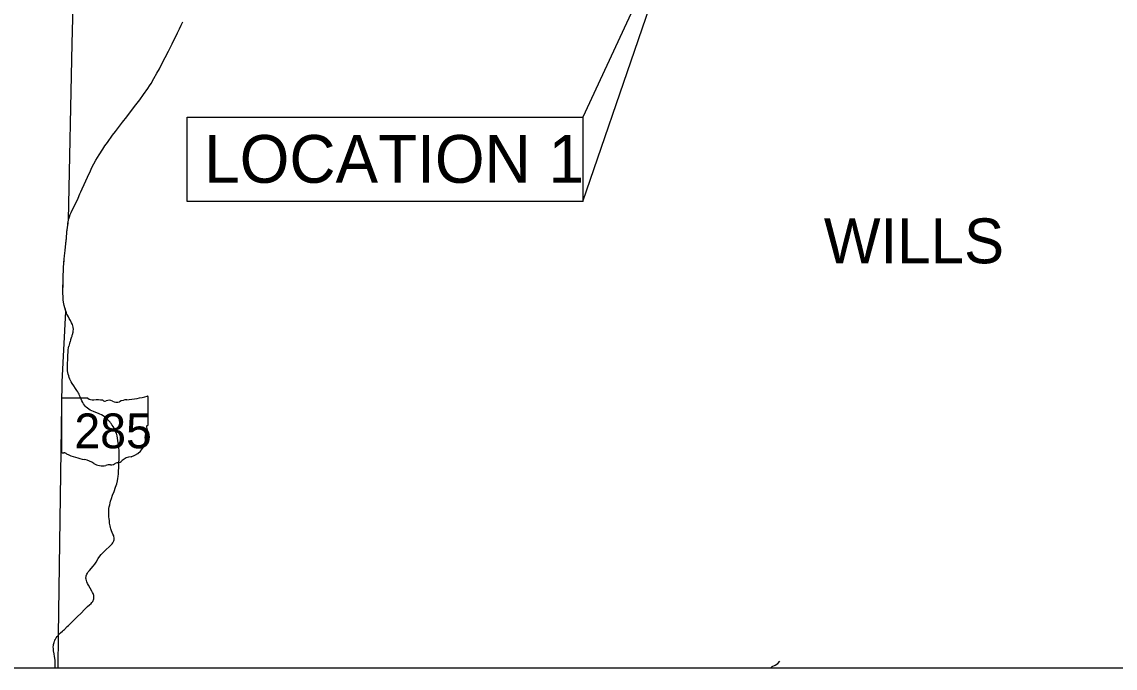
# Model space of a CAD drawing. Extents: x -29.6 to 34, y 0 to 22.
# Drawn here: x -18.092 to -14.201, y 1.053 to 3.352 of the extents above; entities that cross this region are included whole.
import ezdxf

# ---------------------------------------------------------------- set-up
doc = ezdxf.new("R2010")
doc.units = 0
for name, color, linetype in [('BR_P_Gen_Text', 7, 'Continuous'), ('GM_X_Minor_River', 7, 'Continuous'), ('GM_X_State_Location', 7, 'Continuous'), ('GM_X_State_Route', 7, 'Continuous'), ('GM_X_State_Shield', 7, 'Continuous'), ('GM_X_Township', 7, 'Continuous'), ('GM_X_Township_Text', 7, 'Continuous'), ('SH_Text', 7, 'Continuous')]:
    doc.layers.add(name, color=color, linetype=linetype)

msp = doc.modelspace()

# ---------------------------------------------------------------- linework, layer by layer
at = {"layer": 'BR_P_Gen_Text'}
for points in [[(-16.0951, 3.013), (-16.0951, 2.7127), (-15.6989, 3.8667)], [(-17.5038, 3.013), (-16.0951, 3.013), (-16.0951, 2.7127), (-17.5038, 2.7127)]]:
    msp.add_lwpolyline(points, close=True, dxfattribs=at)
at = {"layer": 'GM_X_Minor_River'}
msp.add_lwpolyline([(-15.4272, 1.0528), (-15.4222, 1.0581), (-15.4116, 1.0629), (-15.4017, 1.069), (-15.3947, 1.078)], dxfattribs=at)
at = {"layer": 'GM_X_State_Route'}
for points in [[(-17.8771, 2.7585), (-17.8703, 2.774), (-17.8584, 2.7999), (-17.8478, 2.8226), (-17.8422, 2.8341), (-17.8351, 2.8474), (-17.828, 2.8601), (-17.8167, 2.8791), (-17.8039, 2.8993), (-17.7959, 2.9114), (-17.7875, 2.9232), (-17.7689, 2.9486), (-17.7585, 2.9626), (-17.733, 2.9952), (-17.7185, 3.0142), (-17.6906, 3.0508), (-17.6723, 3.0749), (-17.6586, 3.0937), (-17.6438, 3.1147), (-17.6373, 3.1244), (-17.6317, 3.1333), (-17.6216, 3.1504), (-17.6111, 3.1692), (-17.6023, 3.1857), (-17.5925, 3.2049), (-17.5818, 3.2256), (-17.5702, 3.2484), (-17.5573, 3.2739), (-17.5376, 3.3129), (-17.5307, 3.327), (-17.5246, 3.3403), (-17.5194, 3.3527)], [(-17.9254, 2.6468), (-17.9243, 2.6518), (-17.9222, 2.659), (-17.9196, 2.6667), (-17.9165, 2.6741), (-17.9117, 2.6841), (-17.9058, 2.6954), (-17.9017, 2.7031), (-17.896, 2.7146), (-17.8915, 2.7248), (-17.8851, 2.7398), (-17.8819, 2.7473), (-17.8771, 2.7585)], [(-17.9351, 2.3229), (-17.937, 2.329), (-17.938, 2.3323), (-17.9385, 2.334), (-17.9409, 2.3429), (-17.9423, 2.3485), (-17.9433, 2.3548), (-17.9442, 2.3628), (-17.945, 2.375), (-17.9454, 2.3855), (-17.9455, 2.3895), (-17.9455, 2.3907), (-17.9456, 2.3953), (-17.9456, 2.3999), (-17.9453, 2.4127), (-17.945, 2.4214), (-17.9445, 2.4418), (-17.9432, 2.4744), (-17.9419, 2.497), (-17.9417, 2.4993), (-17.9415, 2.5022), (-17.941, 2.5063), (-17.9408, 2.508), (-17.9395, 2.5195), (-17.9376, 2.5387), (-17.935, 2.563), (-17.9331, 2.5832), (-17.9311, 2.6041), (-17.9292, 2.6203), (-17.9281, 2.629), (-17.9274, 2.6342), (-17.9265, 2.641), (-17.9256, 2.646), (-17.9254, 2.6468)], [(-17.9612, 1.1708), (-17.9586, 1.1735), (-17.9561, 1.1759), (-17.9537, 1.1784), (-17.9473, 1.1843), (-17.9439, 1.1874), (-17.9405, 1.1905), (-17.9299, 1.2005), (-17.9253, 1.2049), (-17.9204, 1.2099), (-17.916, 1.2145), (-17.9118, 1.2185), (-17.9011, 1.2292), (-17.8944, 1.2355), (-17.8812, 1.2481), (-17.8683, 1.2611), (-17.8578, 1.2717), (-17.8505, 1.2784), (-17.8454, 1.2833), (-17.8426, 1.2863), (-17.8397, 1.29), (-17.8379, 1.2932), (-17.8368, 1.296), (-17.8358, 1.2995), (-17.8355, 1.3018), (-17.8354, 1.306), (-17.836, 1.3108), (-17.8371, 1.3148), (-17.8383, 1.3182), (-17.8398, 1.3214), (-17.8428, 1.3271), (-17.8491, 1.3376), (-17.8548, 1.3476), (-17.8581, 1.3541), (-17.8604, 1.3596), (-17.8621, 1.3645), (-17.8632, 1.3688), (-17.8638, 1.3731), (-17.8634, 1.3792), (-17.8626, 1.3816), (-17.8603, 1.3868), (-17.8583, 1.3902), (-17.8552, 1.395), (-17.8513, 1.4), (-17.8377, 1.4157), (-17.8322, 1.4226), (-17.8276, 1.4293), (-17.8197, 1.4423), (-17.8145, 1.4506), (-17.8094, 1.4575), (-17.8051, 1.4621), (-17.8015, 1.4658), (-17.7926, 1.4741), (-17.7797, 1.4858), (-17.7734, 1.4919), (-17.7707, 1.495), (-17.7678, 1.4988), (-17.7656, 1.503), (-17.7647, 1.5052), (-17.7636, 1.5093), (-17.7634, 1.5111), (-17.7631, 1.5165), (-17.7642, 1.5217), (-17.7647, 1.5235), (-17.7675, 1.5299), (-17.7705, 1.5357), (-17.7731, 1.5414), (-17.7753, 1.548), (-17.7767, 1.5536), (-17.7778, 1.5592), (-17.7793, 1.5684), (-17.7804, 1.5776), (-17.7812, 1.584), (-17.7819, 1.5908), (-17.7825, 1.5978), (-17.7828, 1.6058), (-17.7825, 1.6122), (-17.7818, 1.6202), (-17.7806, 1.6271), (-17.7792, 1.6339), (-17.7776, 1.6406), (-17.7757, 1.6473), (-17.7726, 1.6567), (-17.7686, 1.6676), (-17.7636, 1.6813), (-17.7582, 1.6961), (-17.7537, 1.7089), (-17.7509, 1.7194), (-17.7497, 1.7272), (-17.7486, 1.7344), (-17.7478, 1.744), (-17.7461, 1.7759), (-17.7452, 1.8033), (-17.7454, 1.8246), (-17.7464, 1.8389), (-17.75, 1.8624), (-17.7531, 1.8792), (-17.7555, 1.8883), (-17.7583, 1.8947), (-17.7608, 1.9007), (-17.7636, 1.9065), (-17.7668, 1.9121), (-17.77, 1.9171), (-17.7713, 1.919), (-17.7743, 1.9232), (-17.7761, 1.9254), (-17.7778, 1.9276), (-17.7792, 1.9293), (-17.7819, 1.9324), (-17.7871, 1.938), (-17.7921, 1.9429), (-17.7971, 1.9471), (-17.8018, 1.9506), (-17.8079, 1.9542), (-17.8137, 1.9569), (-17.8192, 1.959), (-17.829, 1.9624), (-17.8371, 1.9654), (-17.8429, 1.968), (-17.8484, 1.9709), (-17.8533, 1.9739), (-17.8583, 1.9777), (-17.8623, 1.981), (-17.8659, 1.9847), (-17.8691, 1.9886), (-17.872, 1.9929), (-17.8749, 1.9979), (-17.8779, 2.0041), (-17.8841, 2.0178), (-17.8853, 2.0207), (-17.8864, 2.0231), (-17.8882, 2.0273), (-17.8903, 2.0314), (-17.8926, 2.0355), (-17.8959, 2.0409), (-17.9007, 2.0482), (-17.9073, 2.0576), (-17.9129, 2.0655), (-17.9165, 2.0714), (-17.9192, 2.0764), (-17.9212, 2.0812), (-17.9232, 2.0866), (-17.9249, 2.0926), (-17.9264, 2.0989), (-17.9279, 2.1045), (-17.9289, 2.1104), (-17.9296, 2.1182), (-17.9291, 2.1361), (-17.9286, 2.1515), (-17.928, 2.1672), (-17.9273, 2.1764), (-17.927, 2.181), (-17.9265, 2.1856), (-17.9253, 2.1924), (-17.9241, 2.1979), (-17.9238, 2.1989), (-17.9212, 2.208), (-17.9196, 2.2134), (-17.9192, 2.215), (-17.9177, 2.2199), (-17.917, 2.2226), (-17.9159, 2.2258), (-17.915, 2.229), (-17.9139, 2.2322), (-17.9132, 2.2343), (-17.9128, 2.236), (-17.9122, 2.2376), (-17.9114, 2.2403), (-17.9096, 2.2477), (-17.9087, 2.2535), (-17.9084, 2.2571), (-17.9085, 2.2606), (-17.9087, 2.2624), (-17.9094, 2.2665), (-17.9106, 2.271), (-17.912, 2.2749), (-17.9146, 2.2809), (-17.9188, 2.2892), (-17.9232, 2.2968), (-17.9263, 2.3023), (-17.9297, 2.3089), (-17.9311, 2.3121), (-17.9329, 2.3169), (-17.9341, 2.3202), (-17.9346, 2.3216), (-17.9351, 2.3229)], [(-17.9737, 1.0528), (-17.9734, 1.0592), (-17.9733, 1.0708), (-17.9736, 1.0795), (-17.9743, 1.0883), (-17.9751, 1.0946), (-17.9768, 1.1038), (-17.9787, 1.1141), (-17.9794, 1.1209), (-17.9798, 1.1284), (-17.9792, 1.1334), (-17.9788, 1.1368), (-17.9781, 1.1402), (-17.9768, 1.1445), (-17.9758, 1.1484), (-17.9745, 1.1515), (-17.9738, 1.1531), (-17.9725, 1.1555), (-17.9719, 1.1564), (-17.9709, 1.1584), (-17.9693, 1.1608), (-17.9659, 1.1654), (-17.9617, 1.1702), (-17.9612, 1.1708)]]:
    msp.add_lwpolyline(points, dxfattribs=at)
at = {"layer": 'GM_X_State_Shield'}
for p, q in [((-17.9509, 2.0096), (-17.9509, 1.822)), ((-17.8574, 2.0128), (-17.9479, 2.0128)), ((-17.642, 1.9193), (-17.642, 2.0175)), ((-17.642, 1.9194), (-17.642, 1.9193))]:
    msp.add_line(p, q, dxfattribs=at)
for centre, major_axis, start_param, end_param in [((-17.9474, 2.01), (0.00358, 0), 1.712693, 3.28349), ((-17.8359, 2.0346), (0.0347, 0), 4.042523, 4.731795), ((-17.8244, 1.9075), (0.1246, 0), 1.404758, 1.657858), ((-17.7961, 2.011), (0.01, 0), 3.836095, 5.185415), ((-17.7814, 1.9893), (0.0208, 0), 0.950623, 2.079405), ((-17.7545, 2.019), (0.0251, 0), 4.081561, 5.145723), ((-17.7102, 1.9555), (0.0659, 0), 1.699011, 2.107814), ((-17.752, 2.2686), (0.3277, 0), 4.814394, 5.042369), ((-17.6454, 2.0179), (0.00344, 0), 6.141152, 7.989035), ((-17.6428, 1.9121), (0.00532, 0), 1.883978, 3.671073), ((-17.6766, 1.8997), (0.032, 0), 5.934695, 6.695948), ((-17.6456, 1.919), (0.00368, 0), 5.05454, 6.418171), ((-17.7337, 1.8658), (0.082, 0), 5.101752, 6.440018), ((-17.6296, 1.8783), (0.0232, 0), 2.387724, 3.262537), ((-17.9474, 1.8216), (0.00361, 0), 3.00124, 4.508301), ((-17.9468, 1.8408), (0.0276, 0), 4.665946, 4.897461), ((-17.9412, 1.8112), (0.00994, 0), 0.519207, 1.627899), ((-17.8157, 1.9797), (0.2366, 0), 4.195997, 4.488961), ((-17.8863, 1.7377), (0.074, 0), 0.823519, 1.323587), ((-17.756, 1.8038), (0.0265, 0), 4.937069, 5.64225), ((-17.6991, 1.7693), (0.0449, 0), 1.647645, 2.488434), ((-17.8062, 1.8102), (0.047, 0), 4.026481, 4.996735), ((-17.7791, 1.7454), (0.0386, 0), 1.495662, 1.94098), ((-17.7756, 1.7962), (0.025, 0), 4.691044, 5.507374), ((-17.753, 1.778), (0.00705, 0), 1.147584, 2.315152)]:
    msp.add_ellipse(centre, major_axis=major_axis, ratio=0.8, start_param=start_param, end_param=end_param, dxfattribs=at)
at = {"layer": 'GM_X_Township'}
msp.add_lwpolyline([(-17.9627, 1.0528), (-17.9613, 1.1713), (-17.9488, 2.0717), (-17.9348, 2.3221), (-17.9353, 2.3234), (-17.9372, 2.3295), (-17.9382, 2.3328), (-17.9387, 2.3345), (-17.9411, 2.3434), (-17.9424, 2.349), (-17.9435, 2.3553), (-17.9444, 2.3633), (-17.9452, 2.3755), (-17.9456, 2.386), (-17.9457, 2.39), (-17.9457, 2.3912), (-17.9458, 2.3958), (-17.9458, 2.4004), (-17.9455, 2.4132), (-17.9452, 2.422), (-17.9447, 2.4423), (-17.9434, 2.4749), (-17.9421, 2.4975), (-17.9419, 2.4998), (-17.9416, 2.5027), (-17.9412, 2.5068), (-17.941, 2.5085), (-17.9397, 2.52), (-17.9378, 2.5392), (-17.9351, 2.5635), (-17.9333, 2.5838), (-17.9313, 2.6046), (-17.9294, 2.6208), (-17.9283, 2.6295), (-17.9276, 2.6347), (-17.9267, 2.6415), (-17.9258, 2.6465), (-17.9131, 3.2755), (-17.9063, 3.5005)], dxfattribs=at)
at = {"layer": 'SH_Text'}
msp.add_lwpolyline([(-29.5833, 13.2079), (-10.7478, 13.2079), (-10.7478, 1.0528), (-29.5833, 1.0528)], close=True, dxfattribs=at)

# ---------------------------------------------------------------- texts
at = {"layer": 'BR_P_Gen_Text'}
msp.add_text('LOCATION 1', height=0.17, dxfattribs=at).set_placement((-17.443, 2.7796))
at = {"layer": 'GM_X_State_Location'}
msp.add_text('285', height=0.000178, rotation=0, dxfattribs=at).set_placement((-17.8327, 1.8842))
for s in ['s', 'r']:
    msp.add_text(s, height=0.000178, dxfattribs=at).set_placement((-17.77, 1.8971))
at = {"layer": 'GM_X_State_Shield'}
msp.add_text('285', height=0.1236, dxfattribs=at).set_placement((-17.9049, 1.8352))
at = {"layer": 'GM_X_Township_Text'}
msp.add_text('WILLS', height=0.1598, rotation=0, dxfattribs=at).set_placement((-15.2378, 2.4932))

doc.saveas('drawing.dxf')
